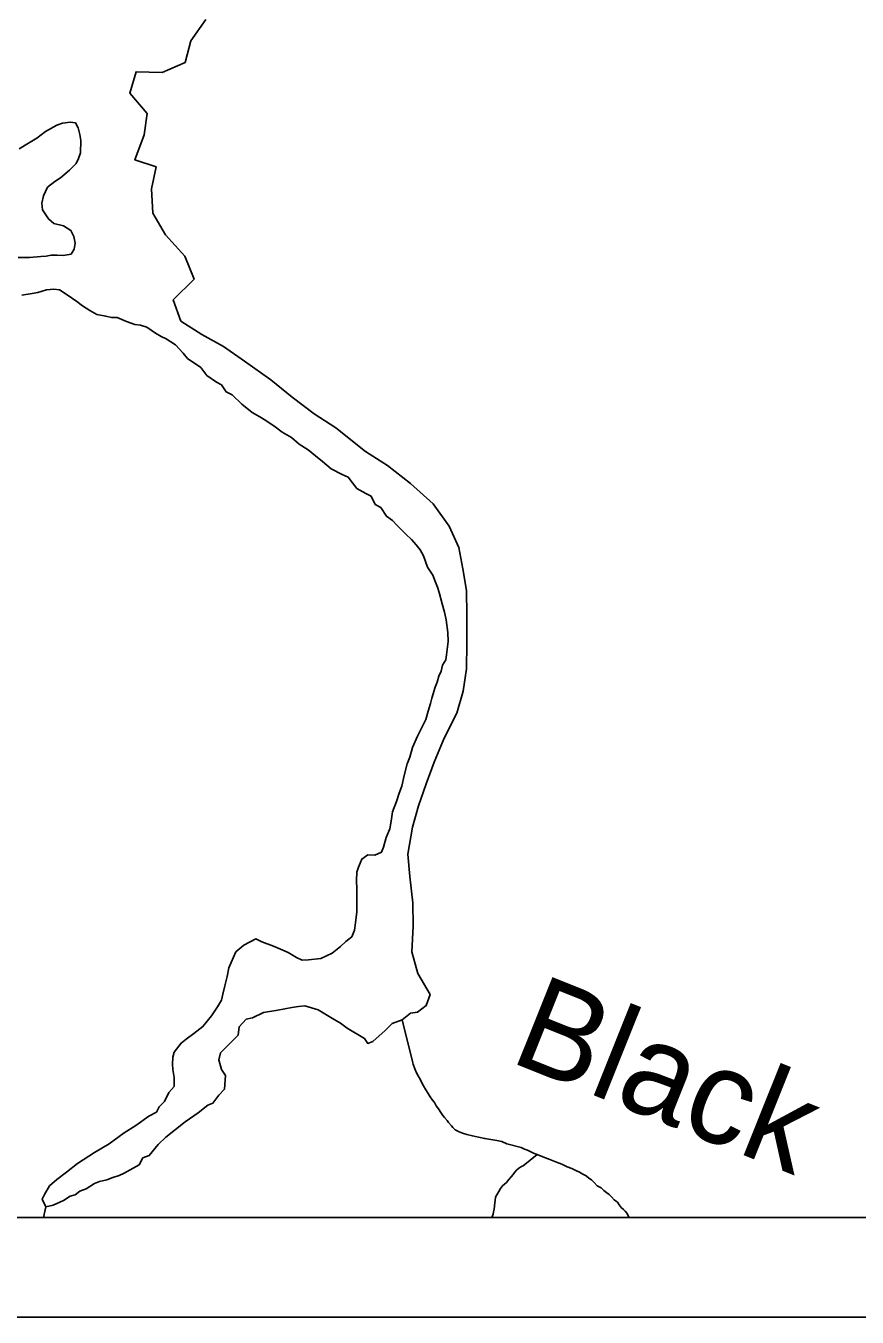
# Model space of a CAD drawing. Extents: x 0 to 34, y 0 to 22.
# Drawn here: x 3.071 to 3.905, y 14.238 to 15.535 of the extents above; entities that cross this region are included whole.
import ezdxf

# ---------------------------------------------------------------- set-up
doc = ezdxf.new("R2010")
doc.units = 0
for name, color, linetype in [('GM_X_County', 7, 'Continuous'), ('GM_X_Major_Lake', 7, 'Continuous'), ('GM_X_Major_River', 7, 'Continuous'), ('GM_X_Minor_River', 7, 'Continuous'), ('GM_X_Minor_River_Text', 7, 'Continuous'), ('GM_X_Township', 7, 'Continuous'), ('SH_Data', 7, 'Continuous')]:
    doc.layers.add(name, color=color, linetype=linetype)

msp = doc.modelspace()

# ---------------------------------------------------------------- linework, layer by layer
at = {"layer": 'GM_X_County'}
msp.add_lwpolyline([(9.1622, 14.342), (9.1622, 21.1385), (2.3622, 21.1385), (2.3622, 14.3385), (9.0003, 14.3385)], dxfattribs=at)
at = {"layer": 'GM_X_Major_Lake'}
for points in [[(3.2262, 15.2385), (3.2184, 15.2597), (3.2394, 15.2805), (3.23, 15.3036), (3.2108, 15.325), (3.198, 15.3469), (3.1966, 15.3712), (3.2013, 15.3933), (3.18, 15.4002), (3.1892, 15.4254), (3.1923, 15.4468), (3.175, 15.4674), (3.1812, 15.4888), (3.2074, 15.488), (3.2304, 15.4982), (3.2362, 15.5199), (3.2511, 15.5414)], [(3.0639, 15.4113), (3.0733, 15.4171), (3.0816, 15.4222), (3.0902, 15.4287), (3.1015, 15.435), (3.1072, 15.4373), (3.1151, 15.4382), (3.1205, 15.4375), (3.1232, 15.4326), (3.1248, 15.4257), (3.1256, 15.4197), (3.1254, 15.4075), (3.1235, 15.4018), (3.1209, 15.3968), (3.1142, 15.3899), (3.1052, 15.3822), (3.0996, 15.3787), (3.0924, 15.3729), (3.0884, 15.3641), (3.0866, 15.3569), (3.0874, 15.35), (3.0932, 15.341), (3.0985, 15.3365), (3.1084, 15.334), (3.1157, 15.3295), (3.1188, 15.3234), (3.12, 15.3166), (3.1189, 15.3105), (3.1159, 15.3055), (3.108, 15.3043), (3.1019, 15.3046), (3.0959, 15.3045), (3.091, 15.3037), (3.0857, 15.3033), (3.0743, 15.3024), (3.0629, 15.3022)], [(3.0664, 15.2646), (3.077, 15.2663), (3.0827, 15.2671), (3.0914, 15.2699), (3.0986, 15.2704)], [(3.0986, 15.2704), (3.1042, 15.2697), (3.1119, 15.2648), (3.1218, 15.2581), (3.1275, 15.2536), (3.1348, 15.2492), (3.1417, 15.2451), (3.1508, 15.2433), (3.1565, 15.2422), (3.1622, 15.2419), (3.1717, 15.2379), (3.18, 15.2349), (3.1857, 15.2342), (3.1918, 15.2324), (3.2006, 15.2264), (3.2063, 15.2231), (3.2113, 15.2205), (3.2208, 15.2145)], [(3.4538, 14.7033), (3.4584, 14.7304), (3.4646, 14.7517), (3.4723, 14.7739), (3.4803, 14.7956), (3.4903, 14.8197), (3.5029, 14.8446), (3.5094, 14.8667), (3.5126, 14.8892), (3.513, 14.9146), (3.5131, 14.9431), (3.5128, 14.9678), (3.5091, 14.9898), (3.5051, 15.011), (3.4954, 15.0326), (3.4792, 15.0548), (3.4566, 15.0754), (3.4336, 15.0934), (3.4115, 15.1075), (3.3817, 15.1311), (3.3599, 15.1452), (3.3377, 15.1621), (3.3163, 15.1793), (3.29, 15.1983), (3.269, 15.2129), (3.2472, 15.2251), (3.2262, 15.2385)], [(3.2208, 15.2145), (3.2285, 15.2063), (3.2327, 15.201), (3.2461, 15.1917), (3.2522, 15.1838), (3.2618, 15.1771), (3.2668, 15.1745), (3.2714, 15.1673), (3.2775, 15.1643), (3.2874, 15.155), (3.2978, 15.1467), (3.3054, 15.1423), (3.3115, 15.1385), (3.3207, 15.1322), (3.3279, 15.127), (3.3371, 15.1214), (3.3447, 15.115), (3.3539, 15.1091), (3.3612, 15.1031), (3.3681, 15.0975), (3.3769, 15.09), (3.3879, 15.0844), (3.394, 15.0818), (3.4028, 15.0705), (3.4116, 15.0653), (3.417, 15.0627), (3.4212, 15.0544), (3.4266, 15.0511), (3.4324, 15.0424), (3.4385, 15.0383), (3.4427, 15.0334), (3.4519, 15.0244), (3.4576, 15.0192), (3.4622, 15.0139), (3.4661, 15.0086), (3.4696, 15.0026), (3.4735, 14.9913), (3.4789, 14.9833), (3.4816, 14.9762), (3.4836, 14.9712), (3.4852, 14.9659), (3.4883, 14.9546), (3.4907, 14.9463), (3.4923, 14.9383), (3.494, 14.9258), (3.4944, 14.9167), (3.4927, 14.9033), (3.492, 14.8984), (3.4887, 14.893), (3.4872, 14.8869), (3.485, 14.882), (3.4832, 14.8759), (3.4813, 14.8709), (3.4781, 14.8598), (3.4766, 14.8545), (3.4744, 14.8469), (3.4719, 14.8385), (3.4685, 14.8316), (3.4634, 14.8216), (3.4586, 14.8102), (3.456, 14.8006), (3.4531, 14.7938), (3.4502, 14.7823), (3.448, 14.7713), (3.4451, 14.7644), (3.4425, 14.756), (3.4385, 14.7457), (3.4371, 14.7362), (3.4357, 14.7286), (3.432, 14.7198), (3.4294, 14.7102), (3.4276, 14.7053), (3.4208, 14.7022), (3.4136, 14.7024), (3.4076, 14.6982), (3.4043, 14.6902), (3.4028, 14.6852), (3.4022, 14.6768), (3.4027, 14.6685), (3.4028, 14.6537), (3.4026, 14.6453), (3.4012, 14.6343), (3.4005, 14.627), (3.3975, 14.6201)], [(3.4763, 14.5622), (3.4639, 14.5834), (3.458, 14.605), (3.4592, 14.6308), (3.4589, 14.6544), (3.4559, 14.6806), (3.4538, 14.7033)], [(3.3975, 14.6201), (3.3915, 14.6155), (3.3863, 14.6105), (3.378, 14.6039), (3.3667, 14.5985), (3.3542, 14.5972), (3.3478, 14.5967), (3.3421, 14.5993), (3.3337, 14.6045), (3.3284, 14.6067), (3.3189, 14.6108), (3.3074, 14.6152), (3.3013, 14.6182), (3.2893, 14.6119), (3.2814, 14.605), (3.2766, 14.5943), (3.2744, 14.5889), (3.2726, 14.5802), (3.2701, 14.571), (3.2683, 14.5626), (3.2668, 14.5565), (3.2627, 14.55), (3.2568, 14.5408), (3.2482, 14.5301), (3.2392, 14.5231), (3.2313, 14.5173), (3.2264, 14.5135), (3.2193, 14.5042), (3.2179, 14.4993), (3.2176, 14.4924), (3.218, 14.4868), (3.2193, 14.4788), (3.2194, 14.47), (3.2141, 14.4639), (3.2097, 14.4547), (3.2044, 14.4493), (3.2015, 14.444), (3.194, 14.4401), (3.1808, 14.4308), (3.1691, 14.4234), (3.1541, 14.4122), (3.1394, 14.4037), (3.1225, 14.3924), (3.1113, 14.3839), (3.1015, 14.3766), (3.0944, 14.37), (3.0892, 14.3616), (3.087, 14.3566), (3.0905, 14.3491), (3.098, 14.3507), (3.1082, 14.3554), (3.115, 14.3596), (3.1199, 14.3612), (3.1248, 14.3647), (3.1312, 14.3671), (3.1394, 14.3725), (3.1443, 14.3745), (3.1519, 14.3761), (3.1579, 14.3784), (3.1643, 14.3804), (3.1692, 14.3828), (3.1843, 14.3913), (3.188, 14.3982), (3.1944, 14.4006), (3.2034, 14.4117), (3.2109, 14.419), (3.2304, 14.4345), (3.2435, 14.4434), (3.2533, 14.4511), (3.2582, 14.4531), (3.2642, 14.4611), (3.2698, 14.4673), (3.2708, 14.481), (3.2669, 14.487), (3.2641, 14.4965), (3.2659, 14.5037), (3.2772, 14.5152), (3.2835, 14.5214), (3.2846, 14.5298), (3.2917, 14.5375), (3.2981, 14.5387), (3.309, 14.5442), (3.3234, 14.5466), (3.3374, 14.5491), (3.3442, 14.5503), (3.3506, 14.5508), (3.3639, 14.5468), (3.3784, 14.5382), (3.3864, 14.5334), (3.3929, 14.5285), (3.4105, 14.5181), (3.4136, 14.5132), (3.4189, 14.5152), (3.4252, 14.5209), (3.4309, 14.5259), (3.438, 14.5333), (3.4482, 14.5368), (3.4564, 14.5434), (3.4636, 14.5446), (3.4722, 14.5512), (3.4763, 14.5622)]]:
    msp.add_lwpolyline(points, dxfattribs=at)
at = {"layer": 'GM_X_Major_River'}
for points in [[(3.2511, 15.5414), (3.2362, 15.5199), (3.2304, 15.4982), (3.2074, 15.488), (3.1812, 15.4888), (3.175, 15.4674), (3.1923, 15.4468), (3.1892, 15.4254), (3.18, 15.4002), (3.2013, 15.3933), (3.1966, 15.3712), (3.198, 15.3469), (3.2108, 15.325), (3.23, 15.3036), (3.2394, 15.2805), (3.2184, 15.2597), (3.2262, 15.2385)], [(3.0629, 15.3022), (3.0743, 15.3024), (3.0857, 15.3033), (3.091, 15.3037), (3.0959, 15.3045), (3.1019, 15.3046), (3.108, 15.3043), (3.1159, 15.3055), (3.1189, 15.3105), (3.12, 15.3166), (3.1188, 15.3234), (3.1157, 15.3295), (3.1084, 15.334), (3.0985, 15.3365), (3.0932, 15.341), (3.0874, 15.35), (3.0866, 15.3569), (3.0884, 15.3641), (3.0924, 15.3729), (3.0996, 15.3787), (3.1052, 15.3822), (3.1142, 15.3899), (3.1209, 15.3968), (3.1235, 15.4018), (3.1254, 15.4075), (3.1256, 15.4197), (3.1248, 15.4257), (3.1232, 15.4326), (3.1205, 15.4375), (3.1151, 15.4382), (3.1072, 15.4373), (3.1015, 15.435), (3.0902, 15.4287), (3.0816, 15.4222), (3.0733, 15.4171), (3.0639, 15.4113)], [(3.0986, 15.2704), (3.0914, 15.2699), (3.0827, 15.2671), (3.077, 15.2663), (3.0664, 15.2646)], [(3.2208, 15.2145), (3.2113, 15.2205), (3.2063, 15.2231), (3.2006, 15.2264), (3.1918, 15.2324), (3.1857, 15.2342), (3.18, 15.2349), (3.1717, 15.2379), (3.1622, 15.2419), (3.1565, 15.2422), (3.1508, 15.2433), (3.1417, 15.2451), (3.1348, 15.2492), (3.1275, 15.2536), (3.1218, 15.2581), (3.1119, 15.2648), (3.1042, 15.2697), (3.0986, 15.2704)], [(3.2262, 15.2385), (3.2472, 15.2251), (3.269, 15.2129), (3.29, 15.1983), (3.3163, 15.1793), (3.3377, 15.1621), (3.3599, 15.1452), (3.3817, 15.1311), (3.4115, 15.1075), (3.4336, 15.0934), (3.4566, 15.0754), (3.4792, 15.0548), (3.4954, 15.0326), (3.5051, 15.011), (3.5091, 14.9898), (3.5128, 14.9678), (3.5131, 14.9431), (3.513, 14.9146), (3.5126, 14.8892), (3.5094, 14.8667), (3.5029, 14.8446), (3.4903, 14.8197), (3.4803, 14.7956), (3.4723, 14.7739), (3.4646, 14.7517), (3.4584, 14.7304), (3.4538, 14.7033)], [(3.3975, 14.6201), (3.4005, 14.627), (3.4012, 14.6343), (3.4026, 14.6453), (3.4028, 14.6537), (3.4027, 14.6685), (3.4022, 14.6768), (3.4028, 14.6852), (3.4043, 14.6902), (3.4076, 14.6982), (3.4136, 14.7024), (3.4208, 14.7022), (3.4276, 14.7053), (3.4294, 14.7102), (3.432, 14.7198), (3.4357, 14.7286), (3.4371, 14.7362), (3.4385, 14.7457), (3.4425, 14.756), (3.4451, 14.7644), (3.448, 14.7713), (3.4502, 14.7823), (3.4531, 14.7938), (3.456, 14.8006), (3.4586, 14.8102), (3.4634, 14.8216), (3.4685, 14.8316), (3.4719, 14.8385), (3.4744, 14.8469), (3.4766, 14.8545), (3.4781, 14.8598), (3.4813, 14.8709), (3.4832, 14.8759), (3.485, 14.882), (3.4872, 14.8869), (3.4887, 14.893), (3.492, 14.8984), (3.4927, 14.9033), (3.4944, 14.9167), (3.494, 14.9258), (3.4923, 14.9383), (3.4907, 14.9463), (3.4883, 14.9546), (3.4852, 14.9659), (3.4836, 14.9712), (3.4816, 14.9762), (3.4789, 14.9833), (3.4735, 14.9913), (3.4696, 15.0026), (3.4661, 15.0086), (3.4622, 15.0139), (3.4576, 15.0192), (3.4519, 15.0244), (3.4427, 15.0334), (3.4385, 15.0383), (3.4324, 15.0424), (3.4266, 15.0511), (3.4212, 15.0544), (3.417, 15.0627), (3.4116, 15.0653), (3.4028, 15.0705), (3.394, 15.0818), (3.3879, 15.0844), (3.3769, 15.09), (3.3681, 15.0975), (3.3612, 15.1031), (3.3539, 15.1091), (3.3447, 15.115), (3.3371, 15.1214), (3.3279, 15.127), (3.3207, 15.1322), (3.3115, 15.1385), (3.3054, 15.1423), (3.2978, 15.1467), (3.2874, 15.155), (3.2775, 15.1643), (3.2714, 15.1673), (3.2668, 15.1745), (3.2618, 15.1771), (3.2522, 15.1838), (3.2461, 15.1917), (3.2327, 15.201), (3.2285, 15.2063), (3.2208, 15.2145)], [(3.4538, 14.7033), (3.4559, 14.6806), (3.4589, 14.6544), (3.4592, 14.6308), (3.458, 14.605), (3.4639, 14.5834), (3.4763, 14.5622)], [(3.4763, 14.5622), (3.4722, 14.5512), (3.4636, 14.5446), (3.4564, 14.5434), (3.4482, 14.5368), (3.438, 14.5333), (3.4309, 14.5259), (3.4252, 14.5209), (3.4189, 14.5152), (3.4136, 14.5132), (3.4105, 14.5181), (3.3929, 14.5285), (3.3864, 14.5334), (3.3784, 14.5382), (3.3639, 14.5468), (3.3506, 14.5508), (3.3442, 14.5503), (3.3374, 14.5491), (3.3234, 14.5466), (3.309, 14.5442), (3.2981, 14.5387), (3.2917, 14.5375), (3.2846, 14.5298), (3.2835, 14.5214), (3.2772, 14.5152), (3.2659, 14.5037), (3.2641, 14.4965), (3.2669, 14.487), (3.2708, 14.481), (3.2698, 14.4673), (3.2642, 14.4611), (3.2582, 14.4531), (3.2533, 14.4511), (3.2435, 14.4434), (3.2304, 14.4345), (3.2109, 14.419), (3.2034, 14.4117), (3.1944, 14.4006), (3.188, 14.3982), (3.1843, 14.3913), (3.1692, 14.3828), (3.1643, 14.3804), (3.1579, 14.3784), (3.1519, 14.3761), (3.1443, 14.3745), (3.1394, 14.3725), (3.1312, 14.3671), (3.1248, 14.3647), (3.1199, 14.3612), (3.115, 14.3596), (3.1082, 14.3554), (3.098, 14.3507), (3.0905, 14.3491), (3.087, 14.3566), (3.0892, 14.3616), (3.0944, 14.37), (3.1015, 14.3766), (3.1113, 14.3839), (3.1225, 14.3924), (3.1394, 14.4037), (3.1541, 14.4122), (3.1691, 14.4234), (3.1808, 14.4308), (3.194, 14.4401), (3.2015, 14.444), (3.2044, 14.4493), (3.2097, 14.4547), (3.2141, 14.4639), (3.2194, 14.47), (3.2193, 14.4788), (3.218, 14.4868), (3.2176, 14.4924), (3.2179, 14.4993), (3.2193, 14.5042), (3.2264, 14.5135), (3.2313, 14.5173), (3.2392, 14.5231), (3.2482, 14.5301), (3.2568, 14.5408), (3.2627, 14.55), (3.2668, 14.5565), (3.2683, 14.5626), (3.2701, 14.571), (3.2726, 14.5802), (3.2744, 14.5889), (3.2766, 14.5943), (3.2814, 14.605), (3.2893, 14.6119), (3.3013, 14.6182), (3.3074, 14.6152), (3.3189, 14.6108), (3.3284, 14.6067), (3.3337, 14.6045), (3.3421, 14.5993), (3.3478, 14.5967), (3.3542, 14.5972), (3.3667, 14.5985), (3.378, 14.6039), (3.3863, 14.6105), (3.3915, 14.6155), (3.3975, 14.6201)]]:
    msp.add_lwpolyline(points, dxfattribs=at)
at = {"layer": 'GM_X_Minor_River'}
for points in [[(3.4482, 14.5368), (3.4584, 14.495), (3.4592, 14.4924), (3.4609, 14.4875), (3.4625, 14.4837), (3.4641, 14.4807), (3.4661, 14.4773), (3.4676, 14.4743), (3.4696, 14.4705), (3.472, 14.4664), (3.4744, 14.463), (3.4764, 14.4596), (3.4787, 14.4563), (3.4807, 14.4537), (3.4823, 14.4503), (3.4846, 14.4473), (3.487, 14.4439), (3.489, 14.4409), (3.4905, 14.4387), (3.4933, 14.4357), (3.4948, 14.4338), (3.4976, 14.4305), (3.4991, 14.4286), (3.5015, 14.4264), (3.5053, 14.4245), (3.5088, 14.4231), (3.513, 14.4217), (3.5187, 14.4203), (3.5249, 14.4189), (3.531, 14.4175), (3.5371, 14.4165), (3.5432, 14.4155), (3.5482, 14.4145), (3.5532, 14.4123), (3.5677, 14.4085), (3.5708, 14.407), (3.5739, 14.4059), (3.5765, 14.4045), (3.58, 14.403), (3.5835, 14.4016), (3.5877, 14.3998), (3.5919, 14.3984), (3.5965, 14.3966), (3.603, 14.394), (3.6084, 14.3919), (3.6138, 14.3893), (3.6184, 14.3875), (3.6226, 14.3857), (3.6261, 14.3839), (3.6296, 14.3817), (3.6327, 14.3803), (3.6354, 14.378), (3.6381, 14.3762), (3.6408, 14.3736), (3.6439, 14.3702), (3.6478, 14.368), (3.6505, 14.3654), (3.6536, 14.3632), (3.6559, 14.3614), (3.6582, 14.3592), (3.661, 14.3562), (3.6641, 14.3536), (3.666, 14.351), (3.668, 14.3483), (3.6703, 14.3465), (3.6719, 14.3446), (3.6739, 14.3424), (3.6754, 14.3394), (3.6761, 14.3385)], [(3.5382, 14.3385), (3.5396, 14.3416), (3.5399, 14.3439), (3.5406, 14.3466), (3.5412, 14.3531), (3.5415, 14.3554), (3.5418, 14.3588), (3.5433, 14.3611), (3.5451, 14.3646), (3.547, 14.3673), (3.5488, 14.37), (3.551, 14.3719), (3.5529, 14.3735), (3.5551, 14.3766), (3.5577, 14.3793), (3.5596, 14.3816), (3.561, 14.3836), (3.5633, 14.3863), (3.5663, 14.3886), (3.5685, 14.3898), (3.5696, 14.3902), (3.5835, 14.4016)], [(3.0883, 14.3385), (3.0905, 14.3491)]]:
    msp.add_lwpolyline(points, dxfattribs=at)
at = {"layer": 'GM_X_Township'}
msp.add_lwpolyline([(2.3622, 19.6335), (2.3622, 14.3385), (4.4492, 14.3385)], dxfattribs=at)
at = {"layer": 'SH_Data'}
msp.add_line((2.2617, 14.2383), (9.2617, 14.2383), dxfattribs=at)

# ---------------------------------------------------------------- texts
at = {"layer": 'GM_X_Minor_River_Text'}
msp.add_text('Black', height=0.09475, rotation=338.2008, dxfattribs=at).set_placement((3.5541, 14.4956))

doc.saveas('drawing.dxf')
